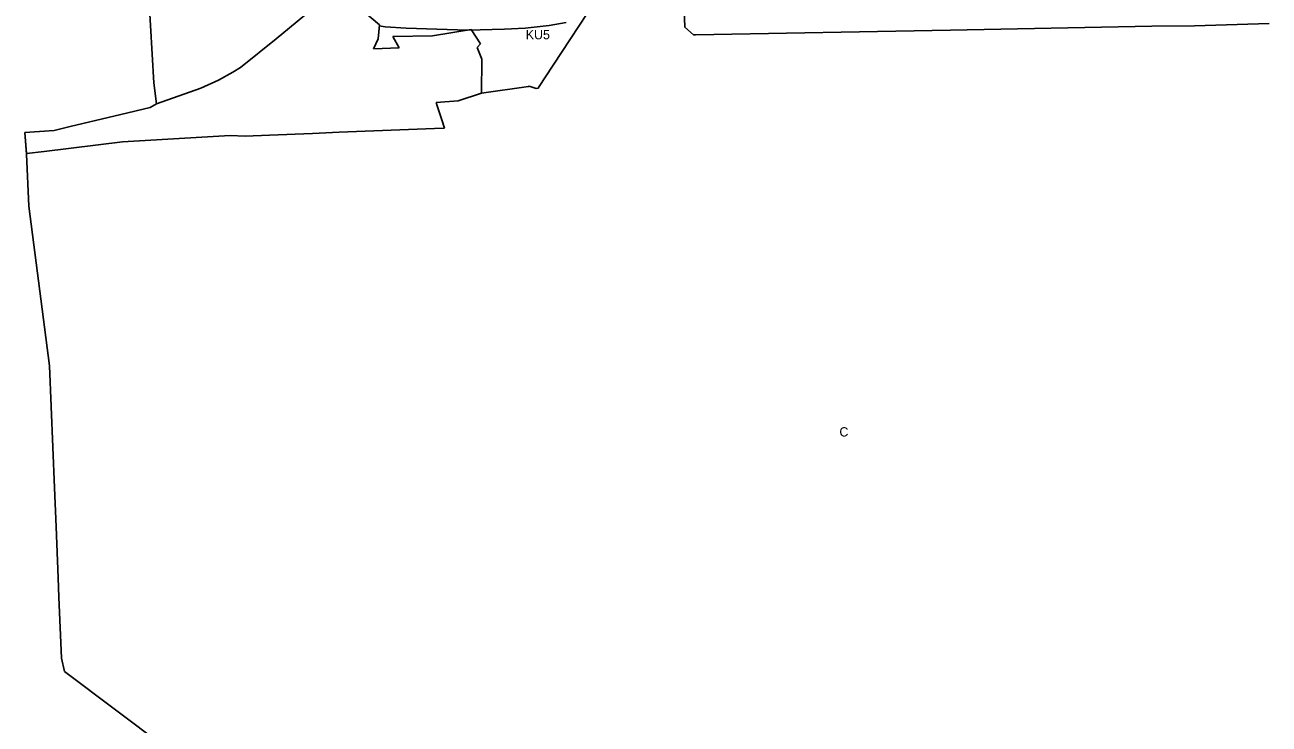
# Model space of a CAD drawing. Extents: x 7428080 to 7432143, y 5545880 to 5549217.
# Drawn here: x 7428612 to 7429356, y 5546705 to 5547123 of the extents above; entities that cross this region are included whole.
import ezdxf

# ---------------------------------------------------------------- set-up
doc = ezdxf.new("R2010")
doc.units = 0
for name, color, linetype in [('CZ_L_granica obszaru objętego planem', 7, 'Continuous'), ('CZ_L_linie rozgraniczające tereny o różnym przeznaczeniu oraz różnych warunkach ich zabudowy i zagospodarowania', 7, 'Continuous'), ('CZ_L_maksymalne nieprzekraczalne linie zabudowy', 7, 'Continuous'), ('CZ_L_opisy_linie rozgraniczające tereny o różnym przeznaczeniu oraz różnych warunkach ich zabudowy i zagospodarowania', 7, 'Continuous')]:
    doc.layers.add(name, color=color, linetype=linetype)

msp = doc.modelspace()

# ---------------------------------------------------------------- linework, layer by layer
at = {"layer": 'CZ_L_granica obszaru objętego planem'}
for p, q in [((7428689.13, 5547088.56), (7428685.6, 5547147.04)), ((7428690.67, 5547075.97), (7428689.13, 5547088.56)), ((7428686.87, 5547073.72), (7428690.67, 5547075.97)), ((7428639.12, 5547062.29), (7428669.32, 5547069.61)), ((7428669.32, 5547069.61), (7428686.87, 5547073.72)), ((7428612, 5547058.86), (7428629.58, 5547059.99)), ((7428629.58, 5547059.99), (7428639.12, 5547062.29)), ((7428612.91, 5547045.9), (7428612, 5547058.86)), ((7428614.39, 5547014.66), (7428612.91, 5547045.9)), ((7428626.74, 5546919.25), (7428614.39, 5547014.66)), ((7428629.64, 5546846.3), (7428626.74, 5546919.25)), ((7428630.63, 5546822.86), (7428629.64, 5546846.3)), ((7428631.89, 5546792.35), (7428630.63, 5546822.86)), ((7428632.29, 5546780.91), (7428631.89, 5546792.35)), ((7428633.88, 5546744.41), (7428632.29, 5546780.91)), ((7428635.63, 5546736.45), (7428633.88, 5546744.41)), ((7428695.87, 5546691.23), (7428635.63, 5546736.45))]:
    msp.add_line(p, q, dxfattribs=at)
at = {"layer": 'CZ_L_linie rozgraniczające tereny o różnym przeznaczeniu oraz różnych warunkach ich zabudowy i zagospodarowania'}
for p, q in [((7428689.13, 5547088.56), (7428685.6, 5547147.04)), ((7428762.2, 5547114.71), (7428782.67, 5547131.66)), ((7428812.73, 5547132.54), (7428823.86, 5547123.08)), ((7428938.04, 5547114.8), (7428948.07, 5547129.89)), ((7428823.86, 5547123.08), (7428823.21, 5547114.88)), ((7428855.66, 5547116.68), (7428878.69, 5547120.45)), ((7428878.69, 5547120.45), (7428884.24, 5547111.72)), ((7428740.89, 5547097.68), (7428762.2, 5547114.71)), ((7428823.21, 5547114.88), (7428820.35, 5547108.76)), ((7428831.88, 5547116.17), (7428855.66, 5547116.68)), ((7428835.64, 5547109.38), (7428831.88, 5547116.17)), ((7428927.66, 5547098.99), (7428938.04, 5547114.8)), ((7428820.35, 5547108.76), (7428835.64, 5547109.38)), ((7428884.24, 5547111.72), (7428882.37, 5547109.57)), ((7428882.37, 5547109.57), (7428885.05, 5547102.58)), ((7428736.24, 5547094.79), (7428740.89, 5547097.68)), ((7428885.05, 5547102.58), (7428884.88, 5547082.25)), ((7428918.9, 5547085.69), (7428927.66, 5547098.99)), ((7428717.14, 5547085.25), (7428727.63, 5547090.09)), ((7428727.63, 5547090.09), (7428736.24, 5547094.79)), ((7428690.67, 5547075.97), (7428689.13, 5547088.56)), ((7428690.67, 5547075.97), (7428717.14, 5547085.25)), ((7428884.88, 5547082.25), (7428870.95, 5547077.79)), ((7428884.88, 5547082.25), (7428912.92, 5547086.26)), ((7428912.92, 5547086.26), (7428913.42, 5547086.43)), ((7428913.42, 5547086.43), (7428917.68, 5547085.14)), ((7428917.68, 5547085.14), (7428918.93, 5547085.38)), ((7428918.93, 5547085.38), (7428918.9, 5547085.69)), ((7428686.87, 5547073.72), (7428690.67, 5547075.97)), ((7428870.95, 5547077.79), (7428857.88, 5547076.66)), ((7428857.88, 5547076.66), (7428858.49, 5547074.81)), ((7428858.49, 5547074.81), (7428861.3, 5547066.31)), ((7428639.12, 5547062.29), (7428669.32, 5547069.61)), ((7428669.32, 5547069.61), (7428686.87, 5547073.72)), ((7428612, 5547058.86), (7428629.58, 5547059.99)), ((7428629.58, 5547059.99), (7428639.12, 5547062.29)), ((7428856.75, 5547061.09), (7428799.93, 5547058.91)), ((7428862.85, 5547061.28), (7428856.75, 5547061.09)), ((7428861.3, 5547066.31), (7428862.85, 5547061.28)), ((7428612.9, 5547046.15), (7428612, 5547058.86)), ((7428670.41, 5547053.28), (7428623.49, 5547047.46)), ((7428700.88, 5547055), (7428670.41, 5547053.28)), ((7428734.63, 5547056.92), (7428700.88, 5547055)), ((7428743.61, 5547056.49), (7428734.63, 5547056.92)), ((7428758.29, 5547057.12), (7428743.61, 5547056.49)), ((7428783.9, 5547058.22), (7428758.29, 5547057.12)), ((7428799.93, 5547058.91), (7428783.9, 5547058.22)), ((7428623.49, 5547047.46), (7428612.9, 5547046.15))]:
    msp.add_line(p, q, dxfattribs=at)
msp.add_lwpolyline([(7428695.96, 5546691.09), (7428695.87, 5546691.23), (7428635.63, 5546736.45), (7428633.88, 5546744.41), (7428632.29, 5546780.91), (7428631.89, 5546792.35), (7428630.63, 5546822.86), (7428629.64, 5546846.3), (7428626.74, 5546919.25), (7428614.39, 5547014.66), (7428612.91, 5547045.9), (7428612.9, 5547046.15)], dxfattribs=at)
at = {"layer": 'CZ_L_maksymalne nieprzekraczalne linie zabudowy'}
for points in [[(7429355.68, 5547123.96), (7429311.09, 5547122.6), (7429285.58, 5547122.29), (7429165.3, 5547119.91), (7429012.92, 5547117.21), (7429011.54, 5547117.27), (7429006.54, 5547121.84), (7429005.69, 5547144.03)], [(7428935.6, 5547124.49), (7428925.35, 5547122.71), (7428911.05, 5547121.15), (7428898.66, 5547120.54), (7428876.74, 5547119.88), (7428858.27, 5547120.58), (7428839.81, 5547121.08), (7428827.24, 5547121.95), (7428823.77, 5547122.52)]]:
    msp.add_lwpolyline(points, dxfattribs=at)

# ---------------------------------------------------------------- texts
at = {"layer": 'CZ_L_opisy_linie rozgraniczające tereny o różnym przeznaczeniu oraz różnych warunkach ich zabudowy i zagospodarowania'}
for s, height, p in [('KU5', 5.549, (7428911.36, 5547114.53)), ('C', 5.55, (7429098.85, 5546876.94))]:
    msp.add_text(s, height=height, dxfattribs=at).set_placement(p)

doc.saveas('drawing.dxf')
